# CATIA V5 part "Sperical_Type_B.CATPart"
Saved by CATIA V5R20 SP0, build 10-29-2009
Part number: Sperical_Type_B
Bounding box of the stored display mesh (mm): x -2.5 to 37.5, y -19.994 to 19.994, z -21.552 to 31.311
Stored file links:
  G:\Khaled_CFAO_2011\SIL\SIL_GR1\gperrin\Khaled\CAD_CATIA\Khaled\Sperical_Type_B.CATPart
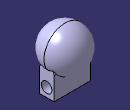
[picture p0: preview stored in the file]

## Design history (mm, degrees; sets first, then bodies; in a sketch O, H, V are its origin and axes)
AxisSystem1: origin (0, 0, 0), X (1, 0, 0), Y (0, 1, 0), Z (0, 0, 1)
Body1 (main body)
  Sketch1 on YZ plane of AxisSystem1, origin (0, 0, 0), H (0, 1, 0), V (0, 0, 1)
    point P1 (-7, -21.5518)
    line L1 (-7, -21.5518) -> (-7, 0)
    point P2 (-7, 0)
    arc A1 centre (-3.5, 0) radius 3.5 from (-7, 0) to (-4.1, 3.4482) cw
    point P4 (-4.1, 3.4482)
    line L2 (-4.1, 3.4482) -> (-5, 3.4482)
    point P5 (-5, 3.4482)
    line L3 (-5, 3.4482) -> (-5, 11.3114)
    point P6 (-5, 11.3114)
    line L4 (-5, 11.3114) -> (0, 11.3114)
    point P7 (0, 11.3114)
    line L5 (-7, -21.5518) -> (0, -21.5518)
    point P8 (0, -21.5518)
    reference intersected line E1 through (0, 0) direction (0, 1) from ZX plane of AxisSystem1
    point P11 (7, -21.5518)
    point P12 (7, 0)
    point P14 (4.1, 3.4482)
    point P15 (5, 3.4482)
    point P16 (5, 11.3114)
    point P17 (0, 11.3114)
    point P18 (0, -21.5518)
    line L6 (7, -21.5518) -> (7, 0)
    arc A2 centre (3.5, 0) radius 3.5 from (7, 0) to (4.1, 3.4482) ccw
    line L7 (4.1, 3.4482) -> (5, 3.4482)
    line L8 (5, 3.4482) -> (5, 11.3114)
    line L9 (5, 11.3114) -> (0, 11.3114)
    line L10 (7, -21.5518) -> (0, -21.5518)
    length L10 = 7
    distance P14 L10 = 25
    length L9 = 5
    coincidence: P2 H, A1 O, P7 V, P8 V, P7 P17, P8 P18
    vertical: L1 V, L3 V
    tangency: A1 L1
    horizontal: L2 H, L4 H, L5 H
    symmetry: P1 P11 E1, P2 P12 E1, P4 P14 E1, P5 P15 E1, P6 P16 E1, P7 P17 E1, P8 P18 E1, L1 L6 E1, A1 A2 E1, L2 L7 E1, L3 L8 E1, L4 L9 E1, L5 L10 E1
  Pad1: profile Sketch1, direction (1, 0, 0), length 35
  Sketch2 on end face of Pad1, origin (35, 0, 0), H (0, 1, 0), V (0, 0, 1)
    circle A1 centre (0, -13) radius 5
    point P1 (0, -13)
    point P2 (0, 0)
    radius A1 = 5
    distance P1 H = 13
    coincidence: P1 V
  Point1: type Center, Curve Sketch2
  Sketch3 on end face of Pad1, origin (35, 0, -5), H (0, 1, 0), V (0, 0, 1)
    point P1 (0, -8)
    reference projected point E1 (0, -8) from Point1
    coincidence: E1 P1
  Hole1: placed by Sketch3, at (35, 0, -13) direction (-1, 0, 0), diameter 10, through (limit type 3)
  Point2: type OnCurve, Support edge [face of Pad1 from Sketch1.L4 | face of Pad1 from Sketch1.L9], Ratio 0.5
  Sphere1: Center Point2, Axis AxisSystem1, Radius 20, Angle1 -45, Angle3 0, Angle4 180
  CloseSurface1: CloseElement Sphere1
